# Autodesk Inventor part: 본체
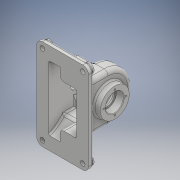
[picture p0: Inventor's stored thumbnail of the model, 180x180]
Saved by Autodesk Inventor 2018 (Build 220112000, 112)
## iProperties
Created: 2024-01
Part Number: 본체
Material: 일반
Document SubType Name: Modeling
Designer: na
Density: 1 g/cm^3
Appearance: 기본값
Author: na
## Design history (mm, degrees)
sketch "스케치1"
  geometry: L1 (-39, -88)-(39, -88); L2 (50, -77)-(50, 77); L3 (39, 88)-(-39, 88); L4 (-50, 77)-(-50, -77); L5 (-50, -88)-(50, 88); L6 (50, -88)-(-50, 88); A1 r 11 centre (39, 77) between (50, 77) and (39, 88); A2 r 11 centre (39, -77) between (39, -88) and (50, -77); A3 r 11 centre (-39, -77) between (-50, -77) and (-39, -88); A4 r 11 centre (-39, 77) between (-39, 88) and (-50, 77); 1 further point
  constraints: 12 end point, 8 point on circle, 8 point on line, 8 tangent, 4 centre point, 3 equal radius, 2 midpoint, 2 parallel, 1 horizontal, 1 perpendicular
  dimensions: "d2" = 11 radius of A1; "d3" = 154 distance of A2.centre A1.centre; "d4" = 78 distance of A4.centre A1.centre
extrude "돌출1" new body sketch "스케치1" distance "d5" = 9; taper "d6" = 0 deg
sketch "스케치2"
  geometry: L1 (0, 0)-(47, 0); L2 (47, 0)-(47, 46); L3 (47, 46)-(0, 46); L4 (0, 46)-(0, 0); L5 (47, 0)-(47, -46); L6 (47, -46)-(0, -46); L7 (0, -46)-(0, 0); A1 r 46 centre (47, 0) between (47, -46) and (47, 46)
  constraints: 14 end point, 3 perpendicular, 2 horizontal, 2 point on circle, 2 point on line, 1 centre point, 1 coincident, 1 tangent, 1 vertical
  dimensions: "d7" = 47 distance of L1.start L1.end; "d8" = 92 diameter of A1
extrude "돌출2" join sketch "스케치2" distance "d9" = 32; taper "d10" = 0 deg
sketch "스케치3"
  geometry: L1 (-9, -77)-(-9, 77) reference; L2 (-9, 0)-(39, 0); L3 (-9, -67.882)-(-9, 67.882); A1 r 72 centre (-33, 0) between (-9, -67.882) and (-9, 67.882); 3 further points
  constraints: 4 end point, 4 point on circle, 2 coincident, 2 point on line, 1 centre point, 1 collinear, 1 horizontal, 1 horizontal alignment, 1 midpoint
  dimensions: "d11" = 48 distance of L2.start L2.end; "d12" = 72 radius of A1
extrude "돌출3" join sketch "스케치3" distance "d13" = 32; taper "d14" = 0 deg
sketch "스케치4"
  geometry: L1 (-77, 0)-(77, 0) reference; L2 (77, 0)-(77, -9) reference; L3 (-77, -9)-(77, -9) reference; L4 (-77, 0)-(-77, -9) reference; L5 (0, -9)-(-46, -9); L6 (0, -9)-(46, -9); L7 (0, -9)-(0, 47); L8 (0, 47)-(-46, 47); L9 (0, 47)-(46, 47); L10 (-46, 0)-(-46, 47) reference; L11 (-46, 47)-(-46, -9); L12 (46, 47)-(46, 0) reference; L13 (46, 47)-(46, -9)
  constraints: 14 end point, 4 point on line, 2 horizontal alignment, 2 vertical, 1 horizontal, 1 midpoint
  dimensions: "d23" = 56 distance of L5.start L7.end
extrude "돌출4" join sketch "스케치4" distance "d24" = 32; taper "d25" = 0 deg
node "작업 평면1"
sketch "스케치5"
  geometry: L1 (-77, -9)-(77, -9) reference; L2 (0, -9)-(0, 47); C1 r 28 at (0, 47); 1 further point
  constraints: 2 end point, 1 centre point, 1 coincident, 1 midpoint, 1 vertical
  dimensions: "d27" = 56 distance of L2.start L2.end; "d28" = 56 diameter of C1
extrude "돌출5" join sketch "스케치5" distance "d29" = 90; taper "d30" = 0 deg
node "작업 평면2"
feature "쉘1" dims "d64" = 5
sketch "스케치14"
  geometry: L1 (34, 22.131)-(34, 42) reference; L2 (12, 22.131)-(34, 22.131) reference; L3 (12, 143.869)-(12, 22.131) reference; L4 (34, 143.869)-(12, 143.869) reference; L5 (34, 124)-(34, 143.869) reference; L6 (66, 124)-(34, 124) reference; L7 (66, 42)-(66, 124) reference; L8 (34, 42)-(66, 42) reference; L9 (-6, 160)-(-6, 6) reference; L10 (0, 0)-(78, 0) reference; L11 (84, 6)-(84, 160) reference; L12 (78, 166)-(0, 166) reference; A1 r 6 centre (0, 6) between (-6, 6) and (0, 0) reference; A2 r 6 centre (78, 6) between (78, 0) and (84, 6) reference; A3 r 6 centre (78, 160) between (84, 160) and (78, 166) reference; A4 r 6 centre (0, 160) between (0, 166) and (-6, 160) reference; 1 further point
extrude "돌출8" join sketch "스케치14" stored distance "d65" = 22; taper "d66" = 0 deg
sketch "스케치15"
  geometry: L1 (-36, -28.991)-(118, -28.991) reference; L2 (-15.124, -7.889)-(97.124, -7.889); L3 (94.674, -12.889)-(-12.674, -12.889); A1 r 72 centre (41, -52.991) between (-5, 2.399) and (-22.992, -19.991) reference; A2 r 72 centre (41, -52.991) between (-15.124, -7.889) and (-26.882, -28.991); A3 r 72 centre (41, -52.991) between (108.882, -28.991) and (97.124, -7.889); A4 r 67 centre (41, -52.991) between (103.554, -28.991) and (94.674, -12.889); A5 r 67 centre (41, -52.991) between (-12.674, -12.889) and (-21.554, -28.991); 1 further point
  constraints: 8 point on circle, 4 centre point, 4 end point, 4 point on line, 1 coincident, 1 horizontal
  dimensions: "d67" = 72 radius of A3; "d68" = 72 radius of A2; "d69" = 21.10107 distance between parallel lines of L2 L1; "d71" = 5 distance between parallel lines of L2 L3; "d72" = 67 radius of A5; "d73" = 67 radius of A4
extrude "돌출9" cut sketch "스케치15" distance "d74" = 22; taper "d75" = 0 deg
sketch "스케치17"
  geometry: C1 r 28 at (0, 0) reference; 1 further point
extrude "돌출10" join sketch "스케치17" distance "d83" = 18; taper "d84" = 0 deg
sketch "스케치18"
  geometry: C1 r 28 at (0, 0) reference; 2 further points
  constraints: 1 coincident
hole "구멍2" sketch "스케치18" at (0, 0) diameter "d85" = 29; stored, may be unused: countersink angle "d89" = 90 deg, drill point angle "d91" = 118 deg; dims "d86" = 6, "d87" = 35, "d88" = 15, "d90" = 18
fillet "모깎기1" dims "d92" = 8
fillet "모깎기2" dims "d93" = 8
fillet "모깎기3" dims "d94" = 8
fillet "모깎기4" dims "d95" = 3
fillet "모깎기5" dims "d96" = 3
fillet "모깎기6" dims "d97" = 3
fillet "모깎기7" dims "d98" = 3
sketch "스케치21"
  geometry: C1 r 9 at (-39, -77); C2 r 9 at (39, -77); A1 r 11 centre (-39, -77) between (-50, -77) and (-39, -88) reference; A2 r 11 centre (39, -77) between (39, -88) and (50, -77) reference; 1 further point
  constraints: 2 centre point, 2 coincident
  dimensions: "d99" = 18 diameter of C1; "d100" = 18 diameter of C2
extrude "돌출11" join sketch "스케치21" distance "d101" = 4; taper "d102" = 0 deg
sketch "스케치22"
  geometry: C1 r 9 at (0, 0) reference; C2 r 9 at (-78, 0) reference; 3 further points
  constraints: 2 coincident
hole "구멍3" sketch "스케치22" at (0, 0), (-78, 0) diameter "d103" = 9; stored, may be unused: countersink angle "d107" = 90 deg, drill point angle "d109" = 118 deg; dims "d104" = 6, "d105" = 35, "d106" = 15, "d108" = 18
fillet "모깎기8" dims "d110" = 3
node "작업 평면4"
sketch "스케치23"
  geometry: L1 (0, 0)-(17, 0); C1 r 6 at (17, 0); 1 further point
  constraints: 2 coincident, 2 end point, 1 centre point, 1 horizontal
  dimensions: "d112" = 17 distance of L1.start L1.end; "d114" = 12 diameter of C1
extrude "돌출12" join sketch "스케치23" stored distance "d115" = 4; taper "d116" = 0 deg
sketch "스케치25"
  geometry: C1 r 6 at (0, 0) reference; 2 further points
  constraints: 1 coincident
hole "구멍4" sketch "스케치25" at (0, 0) diameter "d117" = 5.188; stored, may be unused: countersink angle "d121" = 90 deg, drill point angle "d123" = 118 deg; dims "d118" = 100, "d119" = 8, "d120" = 2, "d122" = 16
node "작업 평면5"
sketch "스케치26"
  geometry: L1 (0, 0)-(-17, 0); C1 r 6 at (-17, 0)
  constraints: 2 end point, 1 centre point, 1 coincident, 1 horizontal
  dimensions: "d125" = 17 distance of L1.start L1.end; "d126" = 12 diameter of C1
extrude "돌출13" join sketch "스케치26" stored distance "d127" = 0; taper "d128" = 0 deg
sketch "스케치27"
  geometry: 3 further points
  constraints: 1 other
  dimensions: "d129" = 17 distance of point (17, 0) point (0, 0); "d130" = 6 distance of point (0, 6) point (0, 0)
hole "구멍5" sketch "스케치27" at (0, 0) diameter "d131" = 5.188; stored, may be unused: countersink angle "d135" = 90 deg, drill point angle "d137" = 118 deg; dims "d132" = 12, "d133" = 8, "d134" = 2, "d136" = 12
sketch "스케치28" dims "d138" = 43
  geometry: L1 (0, 0)-(0, 21.5); C1 r 17.5 at (0, 0) reference; C2 r 28 at (0, 0) reference; 2 further points
  constraints: 2 coincident, 2 end point, 1 vertical, 1 vertical alignment, 2 other
hole "구멍6" sketch "스케치28" at (0, 21.5) diameter "d139" = 3.242; stored, may be unused: countersink angle "d143" = 90 deg, drill point angle "d145" = 118 deg; dims "d140" = 8, "d141" = 8, "d142" = 2, "d144" = 10
chamfer "모따기1" distance "d149" = 1; stored, may be unused: second distance "d150" = 2, angle "d151" = 45 deg
fillet "모깎기9" dims "d152" = 0.6
sketch "스케치29"
  geometry: C1 r 28 at (0, 0) reference; C2 r 28 at (0, 0); 1 further point
  constraints: 1 centre point, 1 coincident, 1 concentric
extrude "돌출14" join sketch "스케치29" distance "d153" = 18; taper "d154" = 0 deg
chamfer "모따기2" distance "d155" = 1; stored, may be unused: second distance "d156" = 2, angle "d157" = 45 deg
fillet "모깎기10" dims "d158" = 0.6
fillet "모깎기11" dims "d159" = 3
fillet "모깎기12" dims "d160" = 3
fillet "모깎기13" dims "d161" = 8
node "솔리드1"
mirror "미러1"
mirror "미러2"
pattern_circular "원형 패턴1" dims angle "d147" = 360 deg
mirror "미러4"
node "투영된 루프2"
node "투영된 루프3"
node "투영된 루프4"
node "투영된 루프5"
other parameters: "d26" = 13, "d31" = -5, "d111" = -106, "d124" = -88
